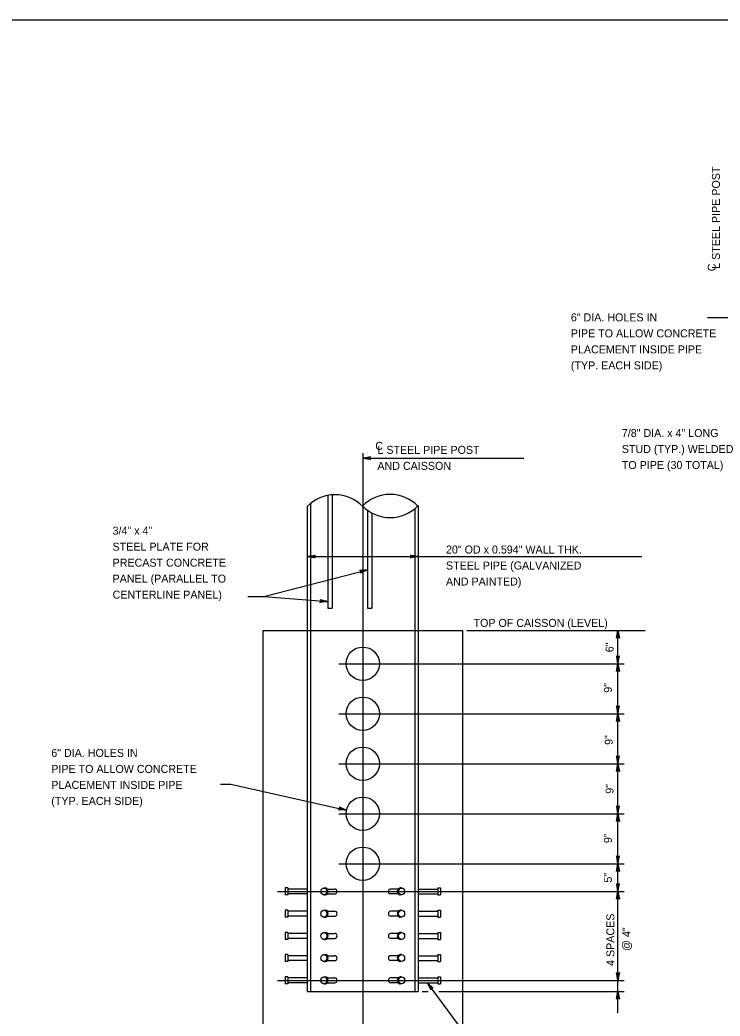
# Model space of a CAD drawing. Extents: x 3475 to 6558, y -3780 to 1166.
# Drawn here: x 4089.1 to 4358.2, y -2795.8 to -2413.3 of the extents above; entities that cross this region are included whole.
import ezdxf

# ---------------------------------------------------------------- set-up
doc = ezdxf.new("R2010")
doc.units = 0
doc.layers.add('1', color=7, linetype='Continuous')
doc.layers.add('2', color=7, linetype='Continuous')

msp = doc.modelspace()

# ---------------------------------------------------------------- linework, layer by layer
at = {"layer": '1'}
for p, q in [((4353.38, -2527.63), (4372.51, -2527.63)), ((4220.89, -2579.66), (4220.89, -2805.95)), ((4220.89, -2581.56), (4282.77, -2581.56)), ((4207.48, -2595.9), (4207.48, -2639.18)), ((4209.08, -2595.69), (4209.08, -2639.18)), ((4199.56, -2600.11), (4199.56, -2786.38)), ((4200.83, -2598.97), (4200.83, -2786.38)), ((4240.96, -2601), (4240.96, -2786.38)), ((4242.22, -2599.82), (4242.22, -2786.38)), ((4222.73, -2601.66), (4222.73, -2639.18)), ((4224.33, -2602.65), (4224.33, -2639.18)), ((4199.56, -2619.34), (4328.16, -2619.34)), ((4182.91, -2634.65), (4222.73, -2624.44)), ((4176.76, -2634.65), (4182.91, -2634.65)), ((4182.91, -2634.65), (4207.48, -2636.69)), ((4207.48, -2639.18), (4209.08, -2639.18)), ((4222.73, -2639.18), (4224.33, -2639.18)), ((4182.49, -2647.71), (4182.49, -2834.94)), ((4182.49, -2647.71), (4199.56, -2647.71)), ((4199.56, -2647.71), (4242.22, -2647.71)), ((4242.22, -2647.71), (4259.29, -2647.71)), ((4259.29, -2647.71), (4259.29, -2834.94)), ((4260.9, -2647.71), (4329.48, -2647.71)), ((4318.96, -2794.57), (4318.96, -2647.71)), ((4211.66, -2660.51), (4321.43, -2660.51)), ((4211.66, -2679.71), (4321.43, -2679.71)), ((4211.66, -2698.91), (4321.43, -2698.91)), ((4166.25, -2706.76), (4170.25, -2706.76)), ((4170.25, -2706.76), (4214.65, -2716.71)), ((4211.66, -2718.11), (4321.43, -2718.11)), ((4211.66, -2737.31), (4321.43, -2737.31)), ((4188.12, -2747.98), (4321.43, -2747.98)), ((4191.03, -2746.64), (4191.03, -2749.31)), ((4192.05, -2746.64), (4191.03, -2746.64)), ((4192.05, -2749.31), (4191.03, -2749.31)), ((4192.05, -2746.64), (4192.05, -2749.31)), ((4199.56, -2747.04), (4192.05, -2747.04)), ((4199.56, -2748.91), (4192.05, -2748.91)), ((4205.96, -2746.64), (4206.47, -2746.64)), ((4205.96, -2749.31), (4206.47, -2749.31)), ((4207.29, -2747.04), (4210.22, -2747.04)), ((4207.29, -2748.91), (4210.22, -2748.91)), ((4234.49, -2747.04), (4231.56, -2747.04)), ((4234.49, -2748.91), (4231.56, -2748.91)), ((4235.83, -2746.64), (4235.31, -2746.64)), ((4235.83, -2749.31), (4235.31, -2749.31)), ((4242.22, -2747.04), (4249.73, -2747.04)), ((4242.22, -2748.91), (4249.73, -2748.91)), ((4249.73, -2746.64), (4249.73, -2749.31)), ((4249.73, -2746.64), (4250.76, -2746.64)), ((4249.73, -2749.31), (4250.76, -2749.31)), ((4250.76, -2746.64), (4250.76, -2749.31)), ((4191.03, -2755.18), (4191.03, -2757.84)), ((4192.05, -2755.18), (4191.03, -2755.18)), ((4192.05, -2757.84), (4191.03, -2757.84)), ((4192.05, -2755.18), (4192.05, -2757.84)), ((4199.56, -2755.58), (4192.05, -2755.58)), ((4199.56, -2757.44), (4192.05, -2757.44)), ((4205.96, -2755.18), (4206.47, -2755.18)), ((4205.96, -2757.84), (4206.47, -2757.84)), ((4207.29, -2755.58), (4210.22, -2755.58)), ((4207.29, -2757.44), (4210.22, -2757.44)), ((4234.49, -2755.58), (4231.56, -2755.58)), ((4234.49, -2757.44), (4231.56, -2757.44)), ((4235.83, -2755.18), (4235.31, -2755.18)), ((4235.83, -2757.84), (4235.31, -2757.84)), ((4242.22, -2755.58), (4249.73, -2755.58)), ((4242.22, -2757.44), (4249.73, -2757.44)), ((4249.73, -2755.18), (4249.73, -2757.84)), ((4249.73, -2755.18), (4250.76, -2755.18)), ((4249.73, -2757.84), (4250.76, -2757.84)), ((4250.76, -2755.18), (4250.76, -2757.84)), ((4191.03, -2763.71), (4191.03, -2766.38)), ((4192.05, -2763.71), (4191.03, -2763.71)), ((4192.05, -2763.71), (4192.05, -2766.38)), ((4199.56, -2764.11), (4192.05, -2764.11)), ((4205.96, -2763.71), (4206.47, -2763.71)), ((4207.29, -2764.11), (4210.22, -2764.11)), ((4234.49, -2764.11), (4231.56, -2764.11)), ((4235.83, -2763.71), (4235.31, -2763.71)), ((4242.22, -2764.11), (4249.73, -2764.11)), ((4249.73, -2763.71), (4249.73, -2766.38)), ((4249.73, -2763.71), (4250.76, -2763.71)), ((4250.76, -2763.71), (4250.76, -2766.38)), ((4192.05, -2766.38), (4191.03, -2766.38)), ((4199.56, -2765.98), (4192.05, -2765.98)), ((4205.96, -2766.38), (4206.47, -2766.38)), ((4207.29, -2765.98), (4210.22, -2765.98)), ((4234.49, -2765.98), (4231.56, -2765.98)), ((4235.83, -2766.38), (4235.31, -2766.38)), ((4242.22, -2765.98), (4249.73, -2765.98)), ((4249.73, -2766.38), (4250.76, -2766.38)), ((4191.03, -2772.24), (4191.03, -2774.91)), ((4192.05, -2772.24), (4191.03, -2772.24)), ((4192.05, -2772.24), (4192.05, -2774.91)), ((4199.56, -2772.64), (4192.05, -2772.64)), ((4205.96, -2772.24), (4206.47, -2772.24)), ((4207.29, -2772.64), (4210.22, -2772.64)), ((4234.49, -2772.64), (4231.56, -2772.64)), ((4235.83, -2772.24), (4235.31, -2772.24)), ((4242.22, -2772.64), (4249.73, -2772.64)), ((4249.73, -2772.24), (4249.73, -2774.91)), ((4249.73, -2772.24), (4250.76, -2772.24)), ((4250.76, -2772.24), (4250.76, -2774.91)), ((4192.05, -2774.91), (4191.03, -2774.91)), ((4199.56, -2774.51), (4192.05, -2774.51)), ((4205.96, -2774.91), (4206.47, -2774.91)), ((4207.29, -2774.51), (4210.22, -2774.51)), ((4234.49, -2774.51), (4231.56, -2774.51)), ((4235.83, -2774.91), (4235.31, -2774.91)), ((4242.22, -2774.51), (4249.73, -2774.51)), ((4249.73, -2774.91), (4250.76, -2774.91)), ((4191.03, -2780.77), (4191.03, -2783.44)), ((4192.05, -2780.77), (4191.03, -2780.77)), ((4192.05, -2780.77), (4192.05, -2783.44)), ((4205.96, -2780.77), (4206.47, -2780.77)), ((4235.83, -2780.77), (4235.31, -2780.77)), ((4249.73, -2780.77), (4249.73, -2783.44)), ((4249.73, -2780.77), (4250.76, -2780.77)), ((4250.76, -2780.77), (4250.76, -2783.44)), ((4188.12, -2782.11), (4321.43, -2782.11)), ((4192.05, -2783.44), (4191.03, -2783.44)), ((4199.56, -2781.17), (4192.05, -2781.17)), ((4199.56, -2783.04), (4192.05, -2783.04)), ((4205.96, -2783.44), (4206.47, -2783.44)), ((4207.29, -2781.17), (4210.22, -2781.17)), ((4207.29, -2783.04), (4210.22, -2783.04)), ((4234.49, -2781.17), (4231.56, -2781.17)), ((4234.49, -2783.04), (4231.56, -2783.04)), ((4235.83, -2783.44), (4235.31, -2783.44)), ((4242.22, -2781.17), (4249.73, -2781.17)), ((4242.22, -2783.04), (4249.73, -2783.04)), ((4267.3, -2812.21), (4245.77, -2783.04)), ((4249.73, -2783.44), (4250.76, -2783.44)), ((4199.56, -2786.38), (4242.22, -2786.38)), ((4243.73, -2786.38), (4246.09, -2786.38)), ((4250.15, -2786.38), (4321.43, -2786.38))]:
    msp.add_line(p, q, dxfattribs=at)
for points in [[(4220.89, -2581.56), (4223.87, -2581), (4223.64, -2581.16), (4223.53, -2581.36), (4223.49, -2581.56), (4223.53, -2581.76), (4223.64, -2581.96), (4223.87, -2582.12), (4220.89, -2581.56), (4223.64, -2581.96), (4223.53, -2581.76), (4220.89, -2581.56), (4223.49, -2581.56), (4223.53, -2581.36), (4220.89, -2581.56), (4223.64, -2581.16)], [(4199.56, -2619.34), (4202.54, -2618.78), (4202.31, -2618.94), (4202.19, -2619.14), (4202.16, -2619.34), (4202.19, -2619.54), (4202.31, -2619.74), (4202.54, -2619.9), (4199.56, -2619.34), (4202.31, -2619.74), (4202.19, -2619.54), (4199.56, -2619.34), (4202.16, -2619.34), (4202.19, -2619.14), (4199.56, -2619.34), (4202.31, -2618.94)], [(4242.22, -2619.34), (4239.24, -2619.9), (4239.47, -2619.74), (4239.59, -2619.54), (4239.62, -2619.34), (4239.59, -2619.14), (4239.47, -2618.94), (4239.24, -2618.78), (4242.22, -2619.34), (4239.47, -2618.94), (4239.59, -2619.14), (4242.22, -2619.34), (4239.62, -2619.34), (4239.59, -2619.54), (4242.22, -2619.34), (4239.47, -2619.74)], [(4222.73, -2624.44), (4219.98, -2625.72), (4220.17, -2625.51), (4220.23, -2625.28), (4220.22, -2625.08), (4220.13, -2624.9), (4219.97, -2624.73), (4219.71, -2624.63), (4222.73, -2624.44), (4219.97, -2624.73), (4220.13, -2624.9), (4222.73, -2624.44), (4220.22, -2625.08), (4220.23, -2625.28), (4222.73, -2624.44), (4220.17, -2625.51)], [(4207.48, -2636.69), (4204.46, -2637), (4204.7, -2636.86), (4204.84, -2636.67), (4204.89, -2636.47), (4204.87, -2636.27), (4204.77, -2636.06), (4204.55, -2635.89), (4207.48, -2636.69), (4204.77, -2636.06), (4204.87, -2636.27), (4207.48, -2636.69), (4204.89, -2636.47), (4204.84, -2636.67), (4207.48, -2636.69), (4204.7, -2636.86)], [(4318.96, -2647.71), (4319.52, -2650.69), (4319.36, -2650.46), (4319.16, -2650.34), (4318.96, -2650.31), (4318.76, -2650.34), (4318.56, -2650.46), (4318.4, -2650.69), (4318.96, -2647.71), (4318.56, -2650.46), (4318.76, -2650.34), (4318.96, -2647.71), (4318.96, -2650.31), (4319.16, -2650.34), (4318.96, -2647.71), (4319.36, -2650.46)], [(4318.96, -2660.51), (4319.52, -2657.53), (4319.36, -2657.76), (4319.16, -2657.87), (4318.96, -2657.91), (4318.76, -2657.87), (4318.56, -2657.76), (4318.4, -2657.53), (4318.96, -2660.51), (4318.56, -2657.76), (4318.76, -2657.87), (4318.96, -2660.51), (4318.96, -2657.91), (4319.16, -2657.87), (4318.96, -2660.51), (4319.36, -2657.76)], [(4318.96, -2660.51), (4319.52, -2663.49), (4319.36, -2663.26), (4319.16, -2663.14), (4318.96, -2663.11), (4318.76, -2663.14), (4318.56, -2663.26), (4318.4, -2663.49), (4318.96, -2660.51), (4318.56, -2663.26), (4318.76, -2663.14), (4318.96, -2660.51), (4318.96, -2663.11), (4319.16, -2663.14), (4318.96, -2660.51), (4319.36, -2663.26)], [(4318.96, -2679.71), (4319.52, -2676.73), (4319.36, -2676.96), (4319.16, -2677.07), (4318.96, -2677.11), (4318.76, -2677.07), (4318.56, -2676.96), (4318.4, -2676.73), (4318.96, -2679.71), (4318.56, -2676.96), (4318.76, -2677.07), (4318.96, -2679.71), (4318.96, -2677.11), (4319.16, -2677.07), (4318.96, -2679.71), (4319.36, -2676.96)], [(4318.96, -2679.71), (4319.52, -2682.69), (4319.36, -2682.46), (4319.16, -2682.34), (4318.96, -2682.31), (4318.76, -2682.34), (4318.56, -2682.46), (4318.4, -2682.69), (4318.96, -2679.71), (4318.56, -2682.46), (4318.76, -2682.34), (4318.96, -2679.71), (4318.96, -2682.31), (4319.16, -2682.34), (4318.96, -2679.71), (4319.36, -2682.46)], [(4318.96, -2698.91), (4319.52, -2695.93), (4319.36, -2696.16), (4319.16, -2696.27), (4318.96, -2696.31), (4318.76, -2696.27), (4318.56, -2696.16), (4318.4, -2695.93), (4318.96, -2698.91), (4318.56, -2696.16), (4318.76, -2696.27), (4318.96, -2698.91), (4318.96, -2696.31), (4319.16, -2696.27), (4318.96, -2698.91), (4319.36, -2696.16)], [(4318.96, -2698.91), (4319.52, -2701.89), (4319.36, -2701.66), (4319.16, -2701.54), (4318.96, -2701.51), (4318.76, -2701.54), (4318.56, -2701.66), (4318.4, -2701.89), (4318.96, -2698.91), (4318.56, -2701.66), (4318.76, -2701.54), (4318.96, -2698.91), (4318.96, -2701.51), (4319.16, -2701.54), (4318.96, -2698.91), (4319.36, -2701.66)], [(4214.65, -2716.71), (4211.61, -2716.6), (4211.87, -2716.5), (4212.03, -2716.33), (4212.11, -2716.14), (4212.12, -2715.94), (4212.05, -2715.72), (4211.86, -2715.51), (4214.65, -2716.71), (4212.05, -2715.72), (4212.12, -2715.94), (4214.65, -2716.71), (4212.11, -2716.14), (4212.03, -2716.33), (4214.65, -2716.71), (4211.87, -2716.5)], [(4318.96, -2718.11), (4319.52, -2715.13), (4319.36, -2715.36), (4319.16, -2715.47), (4318.96, -2715.51), (4318.76, -2715.47), (4318.56, -2715.36), (4318.4, -2715.13), (4318.96, -2718.11), (4318.56, -2715.36), (4318.76, -2715.47), (4318.96, -2718.11), (4318.96, -2715.51), (4319.16, -2715.47), (4318.96, -2718.11), (4319.36, -2715.36)], [(4318.96, -2718.11), (4319.52, -2721.09), (4319.36, -2720.86), (4319.16, -2720.74), (4318.96, -2720.71), (4318.76, -2720.74), (4318.56, -2720.86), (4318.4, -2721.09), (4318.96, -2718.11), (4318.56, -2720.86), (4318.76, -2720.74), (4318.96, -2718.11), (4318.96, -2720.71), (4319.16, -2720.74), (4318.96, -2718.11), (4319.36, -2720.86)], [(4318.96, -2737.31), (4319.52, -2734.33), (4319.36, -2734.56), (4319.16, -2734.67), (4318.96, -2734.71), (4318.76, -2734.67), (4318.56, -2734.56), (4318.4, -2734.33), (4318.96, -2737.31), (4318.56, -2734.56), (4318.76, -2734.67), (4318.96, -2737.31), (4318.96, -2734.71), (4319.16, -2734.67), (4318.96, -2737.31), (4319.36, -2734.56)], [(4318.96, -2737.31), (4319.52, -2740.29), (4319.36, -2740.06), (4319.16, -2739.94), (4318.96, -2739.91), (4318.76, -2739.94), (4318.56, -2740.06), (4318.4, -2740.29), (4318.96, -2737.31), (4318.56, -2740.06), (4318.76, -2739.94), (4318.96, -2737.31), (4318.96, -2739.91), (4319.16, -2739.94), (4318.96, -2737.31), (4319.36, -2740.06)], [(4318.96, -2747.98), (4319.52, -2744.99), (4319.36, -2745.22), (4319.16, -2745.34), (4318.96, -2745.38), (4318.76, -2745.34), (4318.56, -2745.22), (4318.4, -2744.99), (4318.96, -2747.98), (4318.56, -2745.22), (4318.76, -2745.34), (4318.96, -2747.98), (4318.96, -2745.38), (4319.16, -2745.34), (4318.96, -2747.98), (4319.36, -2745.22)], [(4318.96, -2747.98), (4319.52, -2750.96), (4319.36, -2750.73), (4319.16, -2750.61), (4318.96, -2750.58), (4318.76, -2750.61), (4318.56, -2750.73), (4318.4, -2750.96), (4318.96, -2747.98), (4318.56, -2750.73), (4318.76, -2750.61), (4318.96, -2747.98), (4318.96, -2750.58), (4319.16, -2750.61), (4318.96, -2747.98), (4319.36, -2750.73)], [(4318.96, -2782.11), (4318.4, -2779.12), (4318.56, -2779.35), (4318.76, -2779.47), (4318.96, -2779.51), (4319.16, -2779.47), (4319.36, -2779.35), (4319.52, -2779.12), (4318.96, -2782.11), (4319.36, -2779.35), (4319.16, -2779.47), (4318.96, -2782.11), (4318.96, -2779.51), (4318.76, -2779.47), (4318.96, -2782.11), (4318.56, -2779.35)], [(4245.77, -2783.04), (4247.99, -2785.11), (4247.73, -2785.02), (4247.5, -2785.04), (4247.32, -2785.13), (4247.18, -2785.28), (4247.08, -2785.49), (4247.09, -2785.77), (4245.77, -2783.04), (4247.08, -2785.49), (4247.18, -2785.28), (4245.77, -2783.04), (4247.32, -2785.13), (4247.5, -2785.04), (4245.77, -2783.04), (4247.73, -2785.02)], [(4318.96, -2786.38), (4319.52, -2789.36), (4319.36, -2789.13), (4319.16, -2789.01), (4318.96, -2788.98), (4318.76, -2789.01), (4318.56, -2789.13), (4318.4, -2789.36), (4318.96, -2786.38), (4318.56, -2789.13), (4318.76, -2789.01), (4318.96, -2786.38), (4318.96, -2788.98), (4319.16, -2789.01), (4318.96, -2786.38), (4319.36, -2789.13)]]:
    msp.add_lwpolyline(points, dxfattribs=at)
for centre in [(4220.89, -2660.51), (4220.89, -2679.71), (4220.89, -2698.91), (4220.89, -2718.11), (4220.89, -2737.31)]:
    msp.add_circle(centre, 6.4, dxfattribs=at)
for centre, start, end in [((4210.22, -2610.64), 44.6166, 135.3834), ((4231.42, -2610.49), 44.6166, 135.3834), ((4231.42, -2589.44), 224.6166, 315.3834)]:
    msp.add_arc(centre, 14.98, start, end, dxfattribs=at)
for centre in [(4205.96, -2747.98), (4235.83, -2747.98), (4205.96, -2756.51), (4235.83, -2756.51), (4205.96, -2765.04), (4235.83, -2765.04), (4205.96, -2773.57), (4235.83, -2773.57), (4205.96, -2782.11), (4235.83, -2782.11)]:
    msp.add_ellipse(centre, major_axis=(0, 1.33), ratio=0.865643, dxfattribs=at)
for centre, major_axis, ratio, start_param, end_param in [((4206.47, -2747.98), (0, 1.33), 0.865643, 3.141593, 6.283185), ((4210.22, -2747.98), (0, 0.934), 0.876712, 3.141593, 6.283185), ((4231.56, -2747.98), (0, 0.934), 0.876712, 0, 3.141593), ((4235.31, -2747.98), (0, 1.33), 0.865643, 0, 3.141593), ((4206.47, -2756.51), (0, 1.33), 0.865643, 3.141593, 6.283185), ((4210.22, -2756.51), (0, 0.934), 0.876712, 3.141593, 6.283185), ((4231.56, -2756.51), (0, 0.934), 0.876712, 0, 3.141593), ((4235.31, -2756.51), (0, 1.33), 0.865643, 0, 3.141593), ((4206.47, -2765.04), (0, 1.33), 0.865643, 3.141593, 6.283185), ((4210.22, -2765.04), (0, 0.934), 0.876712, 3.141593, 6.283185), ((4231.56, -2765.04), (0, 0.934), 0.876712, 0, 3.141593), ((4235.31, -2765.04), (0, 1.33), 0.865643, 0, 3.141593), ((4206.47, -2773.57), (0, 1.33), 0.865643, 3.141593, 6.283185), ((4210.22, -2773.57), (0, 0.934), 0.876712, 3.141593, 6.283185), ((4231.56, -2773.57), (0, 0.934), 0.876712, 0, 3.141593), ((4235.31, -2773.57), (0, 1.33), 0.865643, 0, 3.141593), ((4206.47, -2782.11), (0, 1.33), 0.865643, 3.141593, 6.283185), ((4235.31, -2782.11), (0, 1.33), 0.865643, 0, 3.141593), ((4210.22, -2782.11), (0, 0.934), 0.876712, 3.141593, 6.283185), ((4231.56, -2782.11), (0, 0.934), 0.876712, 0, 3.141593)]:
    msp.add_ellipse(centre, major_axis=major_axis, ratio=ratio, start_param=start_param, end_param=end_param, dxfattribs=at)
at = {"layer": '2'}
msp.add_line((3801.34, -2413.31), (4587.34, -2413.31), dxfattribs=at)

# ---------------------------------------------------------------- texts
at = {"layer": '1'}
for s, height, p in [('L STEEL PIPE POST', 3.072, (4358.17, -2508.88)), ('C', 3.07, (4356.55, -2509.84)), ('6"', 3.072, (4317.3, -2656.13)), ('9"', 3.072, (4316.66, -2671.67)), ('9"', 3.072, (4316.98, -2691.71)), ('9"', 3.072, (4317.3, -2710.46)), ('9"', 3.072, (4316.66, -2729.42)), ('5"', 3.072, (4316.66, -2744.58)), ('4 SPACES', 3.072, (4317.6, -2776.57)), ('@ 4"', 3.072, (4323.74, -2770.81))]:
    msp.add_text(s, height=height, rotation=90, dxfattribs=at).set_placement(p)
for s, height, p in [('6" DIA. HOLES IN ', 3.072, (4300.88, -2529.07)), ('PIPE TO ALLOW CONCRETE', 3.072, (4300.88, -2535.21)), ('PLACEMENT INSIDE PIPE', 3.072, (4300.88, -2541.36)), ('(TYP. EACH SIDE)', 3.072, (4300.88, -2547.5)), ('7/8" DIA. x 4" LONG', 3.072, (4320.47, -2573.47)), ('C', 3.07, (4225.72, -2578.4)), ('L STEEL PIPE POST', 3.072, (4226.53, -2579.94)), ('STUD (TYP.) WELDED', 3.072, (4320.47, -2579.62)), ('AND CAISSON', 3.072, (4226.53, -2586.08)), ('TO PIPE (30 TOTAL)', 3.072, (4320.47, -2585.76)), ('3/4" x 4"', 3.072, (4124.74, -2610.96)), ('STEEL PLATE FOR ', 3.072, (4124.74, -2617.11)), ('20" OD x 0.594" WALL THK.', 3.072, (4252.88, -2618.21)), ('PRECAST CONCRETE', 3.072, (4124.74, -2623.25)), ('STEEL PIPE (GALVANIZED', 3.072, (4252.88, -2624.35)), ('PANEL (PARALLEL TO', 3.072, (4124.74, -2629.39)), ('AND PAINTED)', 3.072, (4252.88, -2630.5)), ('CENTERLINE PANEL)', 3.072, (4124.74, -2635.54)), ('TOP OF CAISSON (LEVEL)', 3.072, (4263.48, -2646.39)), ('6" DIA. HOLES IN ', 3.072, (4101.19, -2696.32)), ('PIPE TO ALLOW CONCRETE', 3.072, (4101.19, -2702.46)), ('PLACEMENT INSIDE PIPE', 3.072, (4101.19, -2708.6)), ('(TYP. EACH SIDE)', 3.072, (4101.19, -2714.75))]:
    msp.add_text(s, height=height, dxfattribs=at).set_placement(p)

doc.saveas('drawing.dxf')
